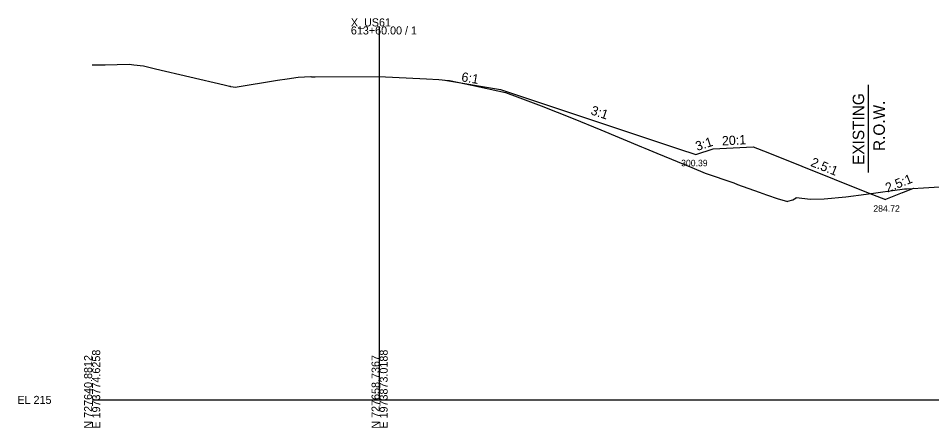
# Model space of a CAD drawing. Extents: x -26 to 1604, y -13 to 9623.
# Drawn here: x -25.7 to 292.1, y 3990.3 to 4132.8 of the extents above; entities that cross this region are included whole.
import ezdxf

# ---------------------------------------------------------------- set-up
doc = ezdxf.new("R2010")
doc.units = 0
for name, color, linetype in [('Draft_XS_Grid', 7, 'Continuous'), ('DTM_X_GROUND', 7, 'Continuous'), ('SLOPE_STAKES_FILL', 7, 'Continuous'), ('XS_CELL', 7, 'Continuous'), ('XS_P_GROUND', 7, 'Continuous'), ('XS_P_TX_DCH', 7, 'Continuous'), ('XS_P_TX_FS_BS', 7, 'Continuous'), ('XS_X_ROW', 7, 'Continuous')]:
    doc.layers.add(name, color=color, linetype=linetype)

msp = doc.modelspace()

# ---------------------------------------------------------------- linework, layer by layer
at = {"layer": 'DTM_X_GROUND'}
msp.add_lwpolyline([(0, 4116.6), (4.55, 4116.67), (12.91, 4116.82), (14.47, 4116.65), (17.85, 4116.32), (22.1, 4115.22), (45.94, 4109.64), (47.79, 4109.2), (47.96, 4109.15), (48.11, 4109.12), (49.04, 4108.92), (49.76, 4108.81), (64.46, 4111.29), (67.89, 4111.81), (71.7, 4112.38), (73.9, 4112.49), (76.1, 4112.62), (76.3, 4112.5), (77.56, 4112.49), (99.78, 4112.53), (116.36, 4111.75), (120.55, 4111.55), (122.84, 4111.3), (124.26, 4111.14), (132.04, 4109.5), (143.75, 4107.05), (147.88, 4105.49), (156.19, 4102.35), (167.37, 4097.95), (177.01, 4094.06), (191.13, 4088.07), (192.25, 4087.58), (196.49, 4085.85), (208.64, 4080.89), (213.23, 4078.97), (223.19, 4075.52), (224.5, 4075.01), (232, 4072.35), (234.58, 4071.42), (238.63, 4069.97), (239.05, 4069.88), (241.85, 4069.1), (242.02, 4069.14), (243.74, 4069.63), (244.88, 4070.39), (244.92, 4070.41), (249.9, 4069.84), (254.62, 4069.99), (262.19, 4070.63), (269.27, 4071.56), (282.55, 4073.44), (282.8, 4073.46), (283.52, 4073.48), (298.58, 4074.42)], dxfattribs=at)
at = {"layer": 'XS_CELL'}
for p, q in [((100, 4000), (100, 4130)), ((0, 4000), (100, 4000)), ((100, 4000), (600, 4000))]:
    msp.add_line(p, q, dxfattribs=at)
at = {"layer": 'XS_P_GROUND'}
for points in [[(122, 4111.39), (142, 4108.06)], [(142, 4108.06), (204, 4087.39), (210, 4085.39), (216, 4087.39), (230, 4088.09), (235, 4086.09)], [(235, 4086.09), (269.95, 4072.12), (275.95, 4069.72)], [(285.71, 4073.62), (285.59, 4073.57), (281.95, 4072.12), (281.8, 4072.06), (275.95, 4069.72)]]:
    msp.add_lwpolyline(points, dxfattribs=at)
at = {"layer": 'XS_X_ROW'}
msp.add_line((270, 4109.67), (270, 4079.13), dxfattribs=at)

# ---------------------------------------------------------------- texts
at = {"layer": 'Draft_XS_Grid'}
msp.add_text('-', height=0.0001, dxfattribs=at).set_placement((0, 4000))
at = {"layer": 'SLOPE_STAKES_FILL'}
for p in [(141.96, 4108), (203.96, 4087.33), (215.96, 4087.33), (229.96, 4088.03), (209.96, 4085.33), (285.67, 4073.56), (269.91, 4072.06), (281.91, 4072.06), (275.91, 4069.66)]:
    msp.add_text('X', height=0.12, dxfattribs=at).set_placement(p)
at = {"layer": 'XS_CELL'}
for s, p in [('X_US61', (90, 4130)), ('613+60.00 / 1', (90, 4127.2)), ('EL 215', (-26, 3998.6))]:
    msp.add_text(s, height=2.8, dxfattribs=at).set_placement(p)
for s, p in [('E 1973774.6258', (2.8, 3990)), ('E 1973873.0188', (102.8, 3990)), ('N 727640.8812', (0, 3990)), ('N 727658.7367', (100, 3990))]:
    msp.add_text(s, height=2.8, rotation=90, dxfattribs=at).set_placement(p)
at = {"layer": 'XS_P_GROUND'}
for p in [(121.96, 4111.33), (234.96, 4086.03)]:
    msp.add_text('X', height=0.12, dxfattribs=at).set_placement(p)
at = {"layer": 'XS_P_TX_DCH'}
for s, p in [('300.39', (204.89, 4081.33)), ('284.72', (271.75, 4065.5))]:
    msp.add_text(s, height=2.25, dxfattribs=at).set_placement(p)
at = {"layer": 'XS_P_TX_FS_BS'}
for s, rotation, p in [('6:1', 350.5377, (128.28, 4110.93)), ('3:1', 341.5651, (173.19, 4099.46)), ('3:1', 18.4349, (210.48, 4086.62)), ('20:1', 2.8624, (219.15, 4088.56)), ('2.5:1', 338.1986, (249.68, 4081.51)), ('2.5:1', 21.8014, (276.7, 4072.16))]:
    msp.add_text(s, height=3.24, rotation=rotation, dxfattribs=at).set_placement(p)
at = {"layer": 'XS_X_ROW'}
for s, p in [('EXISTING', (268.56, 4081.79)), ('R.O.W.', (275.76, 4086.63))]:
    msp.add_text(s, height=4, rotation=90, dxfattribs=at).set_placement(p)

doc.saveas('drawing.dxf')
